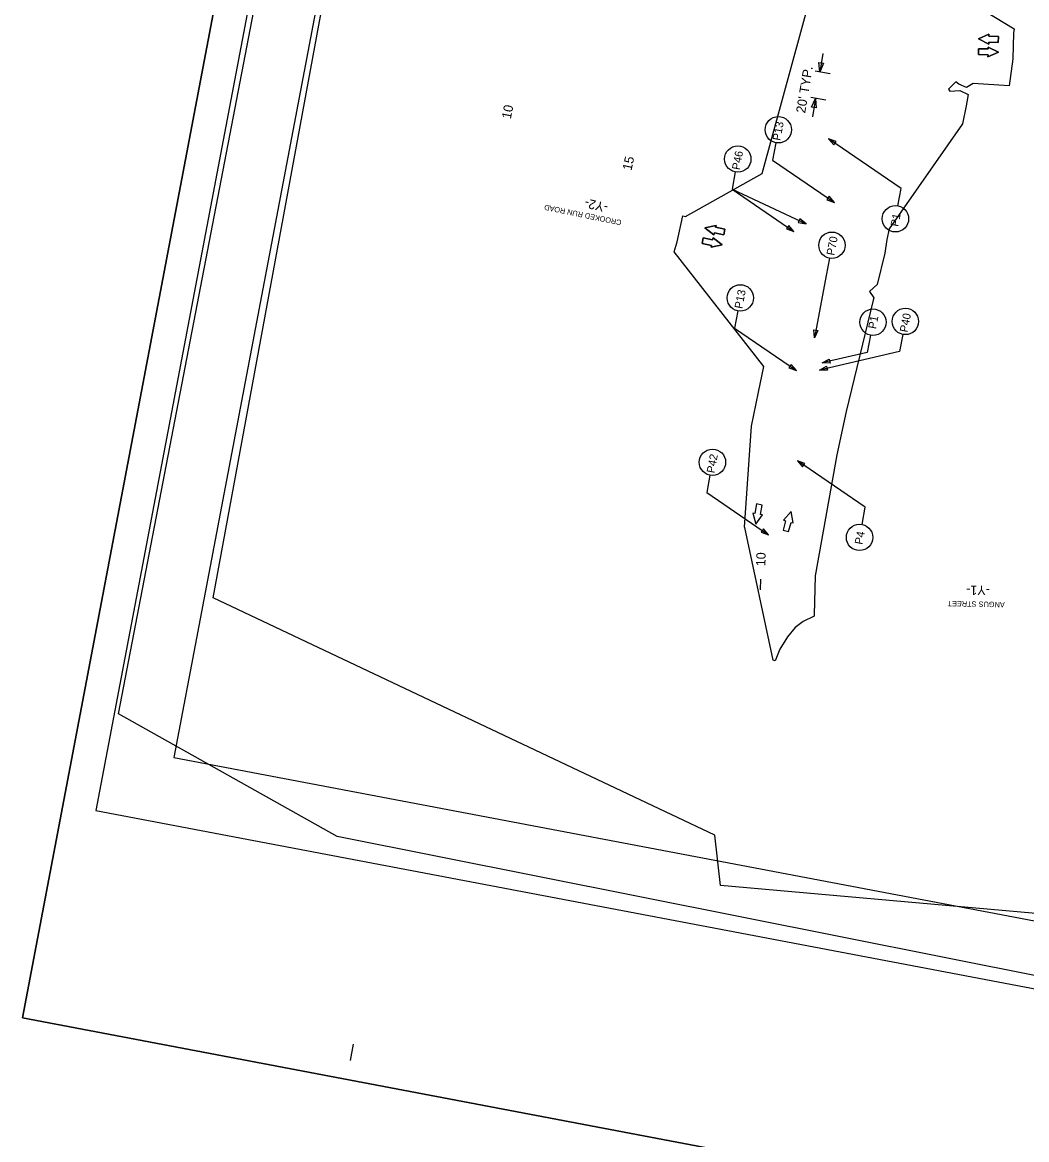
# Model space of a CAD drawing. Extents: x 1615680 to 1617075, y 898420 to 901168.
# Drawn here: x 1615680 to 1616432, y 899419 to 900256 of the extents above; entities that cross this region are included whole.
import ezdxf

# ---------------------------------------------------------------- set-up
doc = ezdxf.new("R2010")
doc.units = 0
for name, color, linetype in [('Default', 7, 'Continuous'), ('DEV BORDER CELL', 7, 'Continuous'), ('DEV DIRECTION OF TRAFFIC FLOW ARROW CELL', 7, 'Continuous'), ('Prop Horizontal Alignment Tick Label', 7, 'Continuous'), ('Prop Horizontal Alignment Tick Large', 7, 'Continuous'), ('Scratch_Level_0', 7, 'Continuous'), ('Scratch_Level_5', 7, 'Continuous'), ('Sheet Clip Boundary CELL', 7, 'Continuous'), ('Sheet Plot Border Outside CELL', 7, 'Continuous'), ('Text', 7, 'Continuous')]:
    doc.layers.add(name, color=color, linetype=linetype)

msp = doc.modelspace()

# ---------------------------------------------------------------- linework, layer by layer
at = {"layer": 'Default'}
msp.add_line((1616211.64, 900131.34), (1616267.08, 900105.31), dxfattribs=at)
for points in [[(1616244.49, 900166.2), (1616242.04, 900153.26), (1616288.43, 900121.49)], [(1616335.98, 900118.94), (1616338.44, 900131.89), (1616283.94, 900169.2)], [(1616214.1, 900144.28), (1616211.64, 900131.34), (1616258.04, 900099.57)], [(1616284.67, 900079.68), (1616282.21, 900066.74), (1616273.41, 900020.01)], [(1616216.02, 900040.19), (1616213.56, 900027.24), (1616259.96, 899995.47)], [(1616339.7, 900022.53), (1616337.24, 900009.59), (1616277.11, 899995.81)], [(1616315.44, 900021.97), (1616312.98, 900009.02), (1616279.13, 900001.27)], [(1616309.07, 899880.06), (1616311.53, 899893), (1616260.63, 899927.86)], [(1616195.11, 899916.94), (1616192.65, 899904), (1616239.05, 899872.22)]]:
    msp.add_lwpolyline(points, dxfattribs=at)
for points in [[(1616289.6, 900167.21), (1616283.94, 900169.2), (1616287.84, 900164.65)], [(1616282.77, 900123.48), (1616288.43, 900121.49), (1616284.53, 900126.04)], [(1616261.18, 900106.37), (1616267.08, 900105.31), (1616262.49, 900109.18)], [(1616252.38, 900101.56), (1616258.04, 900099.57), (1616254.14, 900104.12)], [(1616276.01, 900025.42), (1616273.41, 900020.01), (1616272.96, 900025.99)], [(1616254.3, 899997.47), (1616259.96, 899995.47), (1616256.05, 900000.03)], [(1616283.1, 899995.59), (1616277.11, 899995.81), (1616282.41, 899998.62)], [(1616285.12, 900001.05), (1616279.13, 900001.27), (1616284.43, 900004.08)], [(1616266.28, 899925.86), (1616260.63, 899927.86), (1616264.53, 899923.3)], [(1616233.39, 899874.22), (1616239.05, 899872.22), (1616235.14, 899876.78)]]:
    msp.add_lwpolyline(points, close=True, dxfattribs=at)
for centre in [(1616246.34, 900175.92), (1616215.95, 900154), (1616334.13, 900109.22), (1616286.51, 900089.4), (1616217.86, 900049.91), (1616317.29, 900031.69), (1616341.55, 900032.25), (1616196.95, 899926.66), (1616307.22, 899870.34)]:
    msp.add_circle(centre, 9.89, dxfattribs=at)
at = {"layer": 'DEV BORDER CELL'}
for p, q in [((1615734.93, 899666.51), (1615734.93, 899666.51)), ((1615925.64, 899478.13), (1615927.97, 899490.41))]:
    msp.add_line(p, q, dxfattribs=at)
msp.add_lwpolyline([(1616014.55, 901139.21), (1615734.74, 899665.53), (1616766.32, 899469.67), (1617046.12, 900943.35)], close=True, dxfattribs=at)
at = {"layer": 'DEV DIRECTION OF TRAFFIC FLOW ARROW CELL'}
for p, q in [((1616404.21, 900247.51), (1616396.34, 900244.1)), ((1616396.34, 900244.1), (1616404.21, 900247.51)), ((1616396.34, 900244.1), (1616403.98, 900240.21)), ((1616403.98, 900240.21), (1616396.34, 900244.1)), ((1616403.98, 900240.21), (1616404.03, 900241.69)), ((1616404.03, 900241.69), (1616403.98, 900240.21)), ((1616404.03, 900241.69), (1616411.22, 900241.46)), ((1616411.22, 900241.46), (1616404.03, 900241.69)), ((1616404.16, 900246.03), (1616404.21, 900247.51)), ((1616404.21, 900247.51), (1616404.16, 900246.03)), ((1616411.36, 900245.8), (1616404.16, 900246.03)), ((1616404.16, 900246.03), (1616411.36, 900245.8)), ((1616411.22, 900241.46), (1616411.36, 900245.8)), ((1616411.36, 900245.8), (1616411.22, 900241.46)), ((1616396.44, 900236.72), (1616396.31, 900232.37)), ((1616396.31, 900232.37), (1616396.44, 900236.72)), ((1616396.31, 900232.37), (1616403.5, 900232.14)), ((1616403.5, 900232.14), (1616396.31, 900232.37)), ((1616403.64, 900236.49), (1616396.44, 900236.72)), ((1616396.44, 900236.72), (1616403.64, 900236.49)), ((1616403.46, 900230.67), (1616411.32, 900234.07)), ((1616411.32, 900234.07), (1616403.46, 900230.67)), ((1616403.5, 900232.14), (1616403.46, 900230.67)), ((1616403.46, 900230.67), (1616403.5, 900232.14)), ((1616403.69, 900237.97), (1616403.64, 900236.49)), ((1616403.64, 900236.49), (1616403.69, 900237.97)), ((1616411.32, 900234.07), (1616403.69, 900237.97)), ((1616403.69, 900237.97), (1616411.32, 900234.07)), ((1616199.63, 900104.26), (1616191.29, 900102.3)), ((1616191.29, 900102.3), (1616199.63, 900104.26)), ((1616191.29, 900102.3), (1616198.11, 900097.11)), ((1616198.11, 900097.11), (1616191.29, 900102.3)), ((1616198.11, 900097.11), (1616198.42, 900098.56)), ((1616198.42, 900098.56), (1616198.11, 900097.11)), ((1616198.42, 900098.56), (1616205.46, 900097.06)), ((1616205.46, 900097.06), (1616198.42, 900098.56)), ((1616199.32, 900102.81), (1616199.63, 900104.26)), ((1616199.63, 900104.26), (1616199.32, 900102.81)), ((1616206.36, 900101.31), (1616199.32, 900102.81)), ((1616199.32, 900102.81), (1616206.36, 900101.31)), ((1616205.46, 900097.06), (1616206.36, 900101.31)), ((1616206.36, 900101.31), (1616205.46, 900097.06)), ((1616190.07, 900095.01), (1616189.17, 900090.76)), ((1616189.17, 900090.76), (1616190.07, 900095.01)), ((1616189.17, 900090.76), (1616196.21, 900089.26)), ((1616196.21, 900089.26), (1616189.17, 900090.76)), ((1616197.12, 900093.51), (1616190.07, 900095.01)), ((1616190.07, 900095.01), (1616197.12, 900093.51)), ((1616195.9, 900087.81), (1616204.25, 900089.77)), ((1616204.25, 900089.77), (1616195.9, 900087.81)), ((1616197.42, 900094.96), (1616197.12, 900093.51)), ((1616197.12, 900093.51), (1616197.42, 900094.96)), ((1616204.25, 900089.77), (1616197.42, 900094.96)), ((1616197.42, 900094.96), (1616204.25, 900089.77)), ((1616196.21, 900089.26), (1616195.9, 900087.81)), ((1616195.9, 900087.81), (1616196.21, 900089.26)), ((1616230.03, 899895.4), (1616228.68, 899888.33)), ((1616234.3, 899894.59), (1616230.03, 899895.4)), ((1616232.95, 899887.51), (1616234.3, 899894.59)), ((1616255.91, 899889.66), (1616250.33, 899883.15)), ((1616257.37, 899881.22), (1616255.91, 899889.66)), ((1616228.68, 899888.33), (1616227.23, 899888.6)), ((1616227.23, 899888.6), (1616229.37, 899880.3)), ((1616229.37, 899880.3), (1616234.4, 899887.24)), ((1616234.4, 899887.24), (1616232.95, 899887.51)), ((1616251.76, 899882.76), (1616249.85, 899875.82)), ((1616250.33, 899883.15), (1616251.76, 899882.76)), ((1616254.04, 899874.67), (1616255.95, 899881.61)), ((1616255.95, 899881.61), (1616257.37, 899881.22)), ((1616249.85, 899875.82), (1616254.04, 899874.67))]:
    msp.add_line(p, q, dxfattribs=at)
at = {"layer": 'Prop Horizontal Alignment Tick Large'}
msp.add_line((1616233.07, 899830.96), (1616233.23, 899838.95), dxfattribs=at)
at = {"layer": 'Scratch_Level_0'}
msp.add_lwpolyline([(1616054.34, 901080.76), (1615793.19, 899705.33), (1616726.52, 899528.12), (1616890.46, 900391.55), (1616774.26, 900413.61), (1616871.48, 900925.61)], close=True, dxfattribs=at)
at = {"layer": 'Scratch_Level_5'}
for points in [[(1616273.84, 899841.42), (1616273.25, 899812.18), (1616273.25, 899811.36), (1616264.99, 899807.36), (1616258.95, 899802.9), (1616253.13, 899795.75), (1616247.48, 899786.63), (1616244, 899777.92), (1616242.54, 899778.39), (1616221.34, 899877.87), (1616220.94, 899877.94), (1616226.27, 899953.84), (1616231.37, 899979.34), (1616235.41, 899998.49), (1616168.21, 900084.42), (1616170.51, 900091.83), (1616174.76, 900111.37), (1616176.76, 900111.01), (1616234.19, 900143.08), (1616336.31, 900517.08), (1616337.63, 900527.64), (1616345.35, 900547.71), (1616347.66, 900556.85), (1616364.12, 900697.77)], [(1616393.93, 900269.36), (1616423.1, 900251.65), (1616422.53, 900248.29), (1616422.15, 900229.08), (1616419.46, 900208.99), (1616392.28, 900210.57), (1616387.34, 900207.58), (1616381.58, 900210), (1616379.44, 900211.93), (1616373.9, 900206.3), (1616374.75, 900204.84), (1616382.29, 900205.43), (1616388.66, 900202.44), (1616387.18, 900193.85), (1616384.3, 900180.4), (1616329.37, 900101.79), (1616327.7, 900093.79), (1616326.11, 900083.45), (1616320.49, 900059.92), (1616314.55, 900054.8), (1616317.95, 900049.89), (1616317.48, 900048.25), (1616297.11, 899964.85), (1616290.29, 899932.16), (1616273.84, 899841.42)]]:
    msp.add_lwpolyline(points, dxfattribs=at)
at = {"layer": 'Sheet Clip Boundary CELL'}
for points in [[(1616176.29, 901060.7), (1616848.46, 900914.27), (1616896.28, 900812.91), (1616872.94, 900688.21), (1616835.87, 900695.21), (1616753.94, 900262.18), (1616898.09, 900233.43), (1616734.79, 899562.1), (1616202.98, 899609.43), (1616198.71, 899647.14), (1615822.69, 899825.07), (1616054.34, 901080.76)], [(1616176.29, 901060.7), (1616914, 900899.99), (1616896.28, 900812.91), (1616872.94, 900688.21), (1616835.87, 900695.21), (1616753.94, 900262.18), (1616898.09, 900233.43), (1616747.89, 899480.25), (1615915.8, 899646.19), (1615751.76, 899738.03), (1615981.58, 900932.46), (1616145.94, 900899.57)]]:
    msp.add_lwpolyline(points, close=True, dxfattribs=at)
at = {"layer": 'Sheet Plot Border Outside CELL'}
for points in [[(1616760.47, 899304.87), (1615679.78, 899510.06), (1615994.65, 901168.43), (1617075.34, 900963.24)], [(1616760.47, 899304.87), (1617075.34, 900963.24), (1615994.65, 901168.43), (1615679.78, 899510.06)]]:
    msp.add_lwpolyline(points, close=True, dxfattribs=at)
at = {"layer": 'Text'}
for p, q in [((1616279.65, 900233), (1616277.37, 900219.18)), ((1616285.16, 900217.9), (1616273.92, 900219.75)), ((1616281.9, 900198.17), (1616270.66, 900200.02)), ((1616274.12, 900199.45), (1616271.84, 900185.64))]:
    msp.add_line(p, q, dxfattribs=at)
for points in [[(1616280.24, 900225.81), (1616277.37, 900219.18), (1616276.78, 900226.38)], [(1616271.25, 900192.83), (1616274.12, 900199.45), (1616274.7, 900192.26)]]:
    msp.add_lwpolyline(points, close=True, dxfattribs=at)

# ---------------------------------------------------------------- texts
at = {"layer": 'Default'}
for s, height, rotation, p in [('P13', 6, 79.24933, (1616247.78, 900167.44)), ('P46', 6, 79.24933, (1616217.36, 900145.48)), ('CROOKED RUN ROAD', 4, 168.45796, (1616129.13, 900108.14)), ('P1', 6, 79.24933, (1616336.21, 900102.99)), ('P70', 6, 79.2494, (1616288.24, 900081.36)), ('P13', 6, 79.24933, (1616219.3, 900041.42)), ('P1', 6, 79.2494, (1616319.52, 900026.26)), ('P40', 6, 79.2494, (1616343.13, 900023.75)), ('P42', 6, 79.24933, (1616198.4, 899918.17)), ('P4', 6, 79.24933, (1616309.34, 899864.62)), ('ANGUS STREET', 4, 178.75092, (1616416.09, 899821.87))]:
    msp.add_text(s, height=height, rotation=rotation, dxfattribs=at).set_placement(p)
at = {"layer": 'Prop Horizontal Alignment Tick Label'}
for s, rotation, p in [('10', 78.83642, (1616045.82, 900183.62)), ('15', 77.70978, (1616136.26, 900144.99)), ('-Y2-', 167.14002, (1616119.27, 900120.65)), ('10', 88.56805, (1616236.63, 899848.66)), ('-Y1-', 179.34693, (1616404.88, 899834.04))]:
    msp.add_text(s, height=7, rotation=rotation, dxfattribs=at).set_placement(p)
at = {"layer": 'Text'}
msp.add_text("20' TYP.", height=7, rotation=80.63456, dxfattribs=at).set_placement((1616266.43, 900188.03))

doc.saveas('drawing.dxf')
